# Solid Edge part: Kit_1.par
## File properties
Author: bmolnar
Last saved by: bmolnar
Revision: 76
Sűrűség: 0,000 kg/m^3
Pontosság: 0,990
Username: bmolnar
Dokumentum tartalom típus: 0
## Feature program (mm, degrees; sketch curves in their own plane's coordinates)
base feature "unnamed BaseFeature 1"
sketch for "unnamed Cutout 1" plane through (-0.0012, 0, 85.35) normal (0, 0, -1) x-axis (-1, 0, 0)
  circle centre (-0.0012, 0) radius 8
extrude "unnamed Cutout 1" cut through along -normal
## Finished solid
Body 1: solid body, 46 faces, 63 edges, 49 vertices, 1 internal void.
  Faces by surface: cylinder 16, cone 14, plane 12, torus 4
  Edges by curve: circle 49, line 14
Bounding box of the edges (mm; curved faces can reach further): 68.000 x 67.800 x 14.500, from (-34, -32.35, 85.35) to (34, 35.45, 99.85).
Cylindrical faces by radius (mm): R1.5 x2, R3 x4, R8 x1, R8.27 x1, R8.85 x1, R9 x1, R10.16 x1, R10.25 x1, R19.25 x1, R29.65 x1, R32.35 x1, R34 x1
Conical faces (half-angle, radius in mm at the cone's reference point): 3 deg R10.205 x1, 7 deg R9.5925 x1, 14 deg R8.135 x1, 14 deg R8.4811 x1, 17 deg R8.135 x1, 23 deg R8.829 x1, 42.5 deg R8.1233 x1, 45 deg R9.1 x2, 45 deg R18.75 x1, 84 deg R76.3675 x2, 85 deg R9.9463 x1, 87 deg R8.1765 x1
Toroidal faces (ring radius, tube radius in mm): R8.8057 r0.2025 x1, R9.2522 r0.2925 x1, R9.96 r0.2 x1, R20.05 r0.8 x1
Planar faces by outward normal: +z 7, -z 3, oblique 2
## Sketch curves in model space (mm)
circle centre (0, 0, 85.35) radius 8
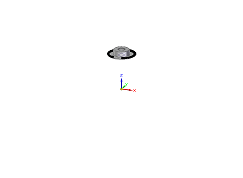
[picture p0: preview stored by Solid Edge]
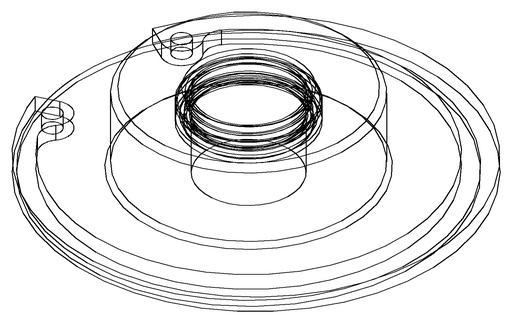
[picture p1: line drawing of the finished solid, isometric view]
